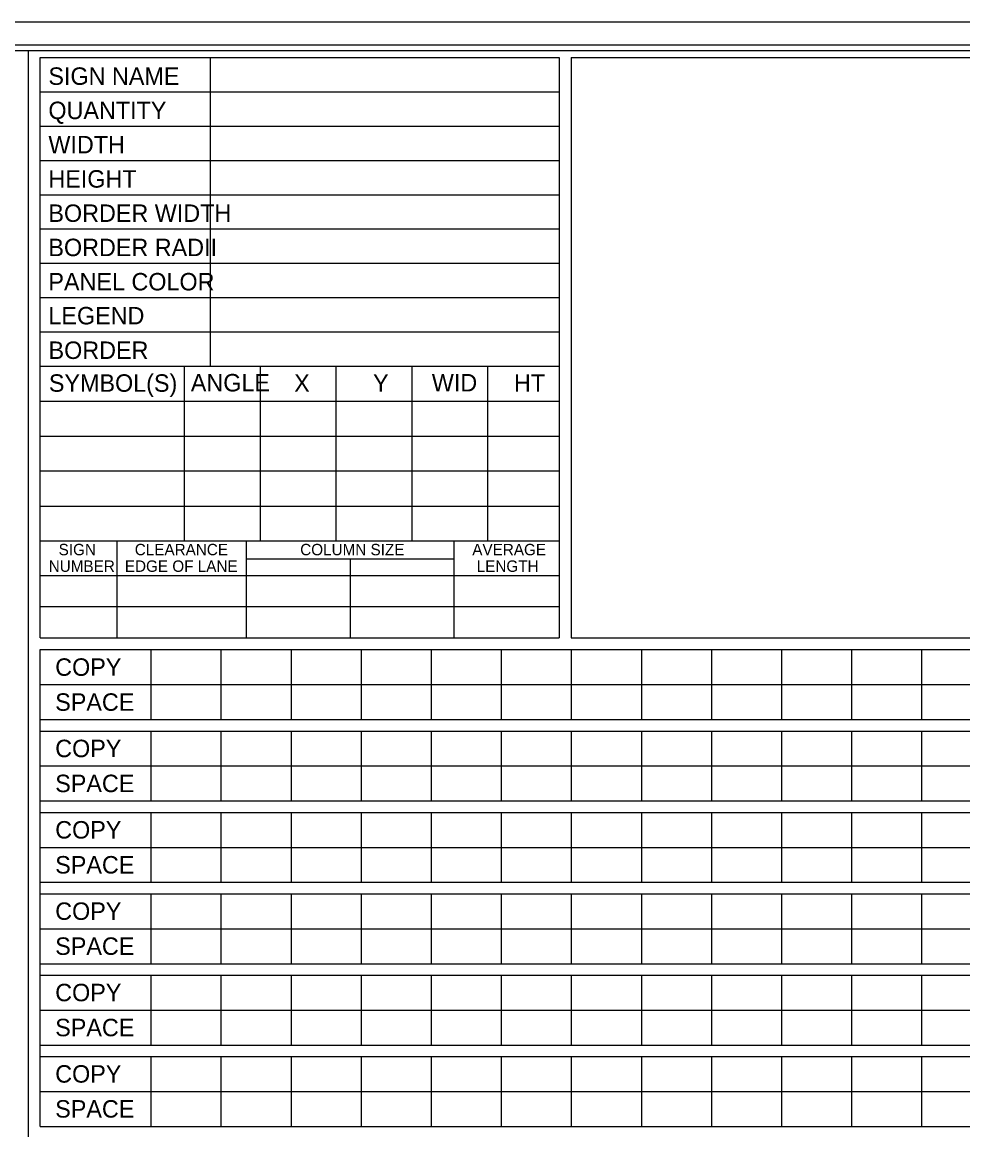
# Model space of a CAD drawing. Extents: x 17890628 to 17890844, y 17897693 to 17898031.
# Drawn here: x 17890772.14 to 17890808.06, y 17897957.5 to 17897999.81 of the extents above; entities that cross this region are included whole.
import ezdxf

# ---------------------------------------------------------------- set-up
doc = ezdxf.new("R2010")
doc.units = 0
for name, color, linetype in [('PlotBorder_dp', 7, 'Continuous'), ('SheetBorder_dp', 7, 'Continuous'), ('SheetLinesMisc2_dp', 7, 'Continuous'), ('TextMinor', 7, 'Continuous')]:
    doc.layers.add(name, color=color, linetype=linetype)

msp = doc.modelspace()

# ---------------------------------------------------------------- linework, layer by layer
at = {"layer": 'PlotBorder_dp'}
msp.add_lwpolyline([(17890700.471, 17897907.61), (17890843.989, 17897907.61), (17890843.989, 17897999.809), (17890700.471, 17897999.809)], close=True, dxfattribs=at)
at = {"layer": 'SheetBorder_dp'}
msp.add_line((17890705.254, 17897998.94), (17890839.205, 17897998.94), dxfattribs=at)
at = {"layer": 'SheetLinesMisc2_dp'}
for p, q in [((17890705.5, 17897998.732), (17890839.233, 17897998.732)), ((17890772.367, 17897998.732), (17890772.367, 17897915.484)), ((17890772.823, 17897976.3), (17890772.823, 17897998.455)), ((17890772.823, 17897998.455), (17890792.654, 17897998.455)), ((17890779.324, 17897998.455), (17890779.324, 17897986.674)), ((17890792.654, 17897998.455), (17890792.654, 17897976.3)), ((17890793.11, 17897998.455), (17890838.594, 17897998.455)), ((17890793.11, 17897998.455), (17890793.11, 17897976.3)), ((17890772.823, 17897997.146), (17890792.654, 17897997.146)), ((17890772.823, 17897995.837), (17890792.654, 17897995.837)), ((17890772.823, 17897994.529), (17890792.654, 17897994.529)), ((17890772.823, 17897993.22), (17890792.654, 17897993.22)), ((17890772.823, 17897991.911), (17890792.654, 17897991.911)), ((17890772.823, 17897990.603), (17890792.654, 17897990.603)), ((17890772.823, 17897989.294), (17890782.738, 17897989.294)), ((17890782.738, 17897989.294), (17890792.654, 17897989.294)), ((17890772.823, 17897987.986), (17890782.738, 17897987.986)), ((17890782.738, 17897987.986), (17890792.654, 17897987.986)), ((17890772.823, 17897986.674), (17890792.654, 17897986.674)), ((17890778.326, 17897986.674), (17890778.326, 17897979.993)), ((17890781.223, 17897986.674), (17890781.223, 17897979.993)), ((17890784.121, 17897986.674), (17890784.121, 17897979.993)), ((17890787.019, 17897986.674), (17890787.019, 17897979.993)), ((17890789.916, 17897986.674), (17890789.916, 17897979.993)), ((17890772.823, 17897985.338), (17890792.654, 17897985.338)), ((17890772.823, 17897984.002), (17890792.654, 17897984.002)), ((17890772.823, 17897982.666), (17890792.654, 17897982.666)), ((17890772.823, 17897981.329), (17890792.654, 17897981.329)), ((17890772.823, 17897979.993), (17890792.654, 17897979.993)), ((17890775.761, 17897979.993), (17890775.761, 17897976.3)), ((17890780.696, 17897979.993), (17890780.696, 17897976.3)), ((17890788.628, 17897979.993), (17890788.628, 17897976.3)), ((17890780.696, 17897979.313), (17890788.628, 17897979.313)), ((17890784.663, 17897979.313), (17890784.663, 17897976.3)), ((17890772.823, 17897978.673), (17890792.654, 17897978.673)), ((17890772.823, 17897977.487), (17890792.654, 17897977.487)), ((17890772.823, 17897976.3), (17890792.654, 17897976.3)), ((17890793.11, 17897976.3), (17890838.594, 17897976.3)), ((17890772.824, 17897957.633), (17890772.824, 17897975.843)), ((17890772.824, 17897975.843), (17890838.594, 17897975.843)), ((17890777.058, 17897975.843), (17890777.058, 17897973.171)), ((17890779.733, 17897975.843), (17890779.733, 17897973.171)), ((17890782.408, 17897975.843), (17890782.408, 17897973.171)), ((17890785.084, 17897975.843), (17890785.084, 17897973.171)), ((17890787.76, 17897975.843), (17890787.76, 17897973.171)), ((17890790.435, 17897975.843), (17890790.435, 17897973.171)), ((17890793.11, 17897975.843), (17890793.11, 17897973.171)), ((17890795.786, 17897975.843), (17890795.786, 17897973.171)), ((17890798.462, 17897975.843), (17890798.462, 17897973.171)), ((17890801.137, 17897975.843), (17890801.137, 17897973.171)), ((17890803.813, 17897975.843), (17890803.813, 17897973.171)), ((17890806.488, 17897975.843), (17890806.488, 17897973.171)), ((17890772.824, 17897974.507), (17890838.594, 17897974.507)), ((17890772.824, 17897973.171), (17890838.594, 17897973.171)), ((17890772.824, 17897972.735), (17890838.594, 17897972.735)), ((17890777.058, 17897972.735), (17890777.058, 17897970.064)), ((17890779.733, 17897972.735), (17890779.733, 17897970.064)), ((17890782.408, 17897972.735), (17890782.408, 17897970.064)), ((17890785.084, 17897972.735), (17890785.084, 17897970.064)), ((17890787.76, 17897972.735), (17890787.76, 17897970.064)), ((17890790.435, 17897972.735), (17890790.435, 17897970.064)), ((17890793.11, 17897972.735), (17890793.11, 17897970.064)), ((17890795.786, 17897972.735), (17890795.786, 17897970.064)), ((17890798.462, 17897972.735), (17890798.462, 17897970.064)), ((17890801.137, 17897972.735), (17890801.137, 17897970.064)), ((17890803.813, 17897972.735), (17890803.813, 17897970.064)), ((17890806.488, 17897972.735), (17890806.488, 17897970.064)), ((17890772.824, 17897971.399), (17890838.594, 17897971.4)), ((17890772.824, 17897970.064), (17890838.594, 17897970.064)), ((17890772.824, 17897969.628), (17890838.594, 17897969.628)), ((17890777.058, 17897969.628), (17890777.058, 17897966.956)), ((17890779.733, 17897969.628), (17890779.733, 17897966.956)), ((17890782.408, 17897969.628), (17890782.408, 17897966.956)), ((17890785.084, 17897969.628), (17890785.084, 17897966.956)), ((17890787.76, 17897969.628), (17890787.76, 17897966.956)), ((17890790.435, 17897969.628), (17890790.435, 17897966.956)), ((17890793.11, 17897969.628), (17890793.11, 17897966.956)), ((17890795.786, 17897969.628), (17890795.786, 17897966.956)), ((17890798.462, 17897969.628), (17890798.462, 17897966.956)), ((17890801.137, 17897969.628), (17890801.137, 17897966.956)), ((17890803.813, 17897969.628), (17890803.813, 17897966.956)), ((17890806.488, 17897969.628), (17890806.488, 17897966.956)), ((17890772.824, 17897968.292), (17890838.594, 17897968.292)), ((17890772.824, 17897966.956), (17890838.594, 17897966.956)), ((17890772.824, 17897966.52), (17890838.594, 17897966.52)), ((17890777.058, 17897966.52), (17890777.058, 17897963.848)), ((17890779.733, 17897966.52), (17890779.733, 17897963.848)), ((17890782.408, 17897966.52), (17890782.408, 17897963.848)), ((17890785.084, 17897966.52), (17890785.084, 17897963.848)), ((17890787.76, 17897966.52), (17890787.76, 17897963.848)), ((17890790.435, 17897966.52), (17890790.435, 17897963.848)), ((17890793.11, 17897966.52), (17890793.11, 17897963.848)), ((17890795.786, 17897966.52), (17890795.786, 17897963.848)), ((17890798.462, 17897966.52), (17890798.462, 17897963.848)), ((17890801.137, 17897966.52), (17890801.137, 17897963.848)), ((17890803.813, 17897966.52), (17890803.813, 17897963.848)), ((17890806.488, 17897966.52), (17890806.488, 17897963.848)), ((17890772.824, 17897965.184), (17890838.594, 17897965.184)), ((17890772.824, 17897963.848), (17890838.594, 17897963.848)), ((17890772.824, 17897963.412), (17890838.594, 17897963.412)), ((17890777.058, 17897963.412), (17890777.058, 17897960.74)), ((17890779.733, 17897963.412), (17890779.733, 17897960.74)), ((17890782.408, 17897963.412), (17890782.408, 17897960.74)), ((17890785.084, 17897963.412), (17890785.084, 17897960.74)), ((17890787.76, 17897963.412), (17890787.76, 17897960.74)), ((17890790.435, 17897963.412), (17890790.435, 17897960.74)), ((17890793.11, 17897963.412), (17890793.11, 17897960.74)), ((17890795.786, 17897963.412), (17890795.786, 17897960.74)), ((17890798.462, 17897963.412), (17890798.462, 17897960.74)), ((17890801.137, 17897963.412), (17890801.137, 17897960.74)), ((17890803.813, 17897963.412), (17890803.813, 17897960.74)), ((17890806.488, 17897963.412), (17890806.488, 17897960.74)), ((17890772.824, 17897962.076), (17890838.594, 17897962.076)), ((17890772.824, 17897960.74), (17890838.594, 17897960.74)), ((17890772.824, 17897960.304), (17890838.594, 17897960.304)), ((17890777.058, 17897960.304), (17890777.058, 17897957.633)), ((17890779.733, 17897960.304), (17890779.733, 17897957.633)), ((17890782.408, 17897960.304), (17890782.408, 17897957.633)), ((17890785.084, 17897960.304), (17890785.084, 17897957.633)), ((17890787.76, 17897960.304), (17890787.76, 17897957.633)), ((17890790.435, 17897960.304), (17890790.435, 17897957.633)), ((17890793.11, 17897960.304), (17890793.11, 17897957.633)), ((17890795.786, 17897960.304), (17890795.786, 17897957.633)), ((17890798.462, 17897960.304), (17890798.462, 17897957.633)), ((17890801.137, 17897960.304), (17890801.137, 17897957.633)), ((17890803.813, 17897960.304), (17890803.813, 17897957.633)), ((17890806.488, 17897960.304), (17890806.488, 17897957.633)), ((17890772.824, 17897958.969), (17890838.594, 17897958.969)), ((17890772.824, 17897957.633), (17890838.594, 17897957.633))]:
    msp.add_line(p, q, dxfattribs=at)

# ---------------------------------------------------------------- texts
at = {"layer": 'TextMinor'}
for s, height, p in [('SIGN NAME', 0.6667, (17890773.142, 17897997.415)), ('QUANTITY', 0.6667, (17890773.142, 17897996.106)), ('WIDTH', 0.6667, (17890773.142, 17897994.798)), ('HEIGHT', 0.6667, (17890773.142, 17897993.489)), ('BORDER WIDTH', 0.66667, (17890773.142, 17897992.18)), ('BORDER RADII', 0.66667, (17890773.142, 17897990.872)), ('PANEL COLOR', 0.66667, (17890773.142, 17897989.563)), ('LEGEND', 0.6667, (17890773.142, 17897988.266)), ('BORDER', 0.6667, (17890773.148, 17897986.946)), ('SYMBOL(S)', 0.6667, (17890773.16, 17897985.692)), ('ANGLE', 0.6667, (17890778.581, 17897985.705)), ('X', 0.667, (17890782.527, 17897985.692)), ('Y', 0.667, (17890785.54, 17897985.692)), ('WID', 0.6667, (17890787.784, 17897985.705)), ('HT', 0.6667, (17890790.925, 17897985.693)), ('SIGN', 0.4357, (17890773.533, 17897979.448)), ('CLEARANCE', 0.4357, (17890776.44, 17897979.447)), ('COLUMN SIZE', 0.43573, (17890782.758, 17897979.447)), ('AVERAGE', 0.4357, (17890789.33, 17897979.447)), ('NUMBER', 0.4357, (17890773.154, 17897978.814)), ('EDGE OF LANE', 0.43573, (17890776.061, 17897978.814)), ('LENGTH', 0.4357, (17890789.498, 17897978.814)), ('COPY', 0.6667, (17890773.402, 17897974.843)), ('SPACE', 0.6667, (17890773.402, 17897973.507)), ('COPY', 0.6667, (17890773.402, 17897971.736)), ('SPACE', 0.6667, (17890773.402, 17897970.4)), ('COPY', 0.6667, (17890773.402, 17897968.628)), ('SPACE', 0.6667, (17890773.402, 17897967.292)), ('COPY', 0.6667, (17890773.402, 17897965.521)), ('SPACE', 0.6667, (17890773.402, 17897964.185)), ('COPY', 0.6667, (17890773.402, 17897962.413)), ('SPACE', 0.6667, (17890773.402, 17897961.076)), ('COPY', 0.6667, (17890773.402, 17897959.305)), ('SPACE', 0.6667, (17890773.402, 17897957.969))]:
    msp.add_text(s, height=height, dxfattribs=at).set_placement(p)

doc.saveas('drawing.dxf')
